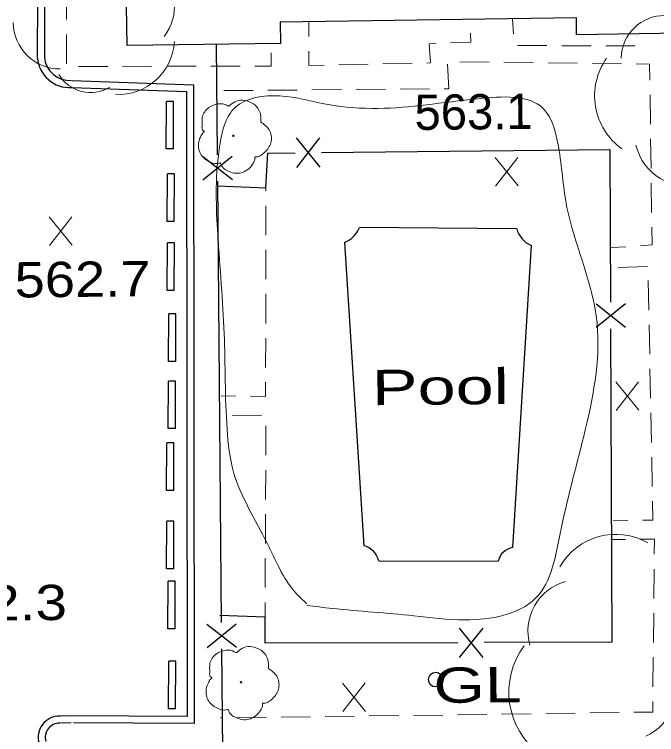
# Model space of a CAD drawing. Extents: x 2361708 to 2370558, y 6977955 to 6991887.
# Drawn here: x 2365980.4 to 2366067.7, y 6986283.8 to 6986381.8 of the extents above; entities that cross this region are included whole.
import ezdxf

# ---------------------------------------------------------------- set-up
doc = ezdxf.new("R2010")
doc.units = 0
doc.header["$LTSCALE"] = 1.9
for name, color, linetype, lineweight in [('11', 7, 'Continuous', 25), ('13', 7, 'Continuous', 13), ('17', 7, 'Continuous', 25), ('2', 7, 'Continuous', 25), ('20', 7, 'Continuous', 25), ('23', 7, 'Continuous', 25), ('29', 7, 'Continuous', 13), ('31', 7, 'Continuous', 13), ('35', 7, 'Continuous', 13)]:
    doc.layers.add(name, color=color, linetype=linetype, lineweight=lineweight)

msp = doc.modelspace()

# ---------------------------------------------------------------- linework, layer by layer
at = {"layer": '11'}
msp.add_lwpolyline([(2366137.4, 6986379.684), (2366107.662, 6986379.311), (2366107.635, 6986381.121), (2366090.917, 6986380.861), (2366090.94, 6986379.542), (2366056.863, 6986378.997), (2366056.831, 6986381.327), (2366016.544, 6986380.754), (2366016.581, 6986377.854), (2365995.733, 6986377.546), (2365995.617, 6986385.604), (2365997.517, 6986385.633), (2365996.969, 6986420.089), (2366039.844, 6986420.767), (2366039.946, 6986414.288), (2366105.78, 6986415.284), (2366105.76, 6986416.304), (2366136.797, 6986416.81)], close=True, dxfattribs=at)
at = {"layer": '13'}
for p, q in [((2365987.512, 6986385.077), (2365987.499, 6986381.077)), ((2366048.162, 6986381.145), (2366048.301, 6986379.146)), ((2366020.444, 6986380.781), (2366020.443, 6986378.781)), ((2365987.489, 6986379.077), (2365987.477, 6986375.077)), ((2366048.836, 6986377.561), (2366052.836, 6986377.549)), ((2366054.837, 6986377.538), (2366058.837, 6986377.526)), ((2366030.519, 6986375.056), (2366034.518, 6986375.144)), ((2366044.977, 6986375.304), (2366040.977, 6986375.346)), ((2366050.978, 6986375.231), (2366046.978, 6986375.283)), ((2366056.979, 6986375.158), (2366052.979, 6986375.21)), ((2366062.98, 6986375.085), (2366058.98, 6986375.137)), ((2365989.12, 6986374.722), (2365993.12, 6986374.73)), ((2365995.12, 6986374.729), (2365999.12, 6986374.738)), ((2366001.12, 6986374.747), (2366005.121, 6986374.755)), ((2366007.121, 6986374.754), (2366011.121, 6986374.762)), ((2366024.52, 6986374.939), (2366028.519, 6986375.017)), ((2366012.872, 6986371.458), (2366008.872, 6986371.43)), ((2366018.872, 6986371.505), (2366014.872, 6986371.477)), ((2366024.872, 6986371.562), (2366020.872, 6986371.524)), ((2366030.872, 6986371.609), (2366026.872, 6986371.581)), ((2366036.872, 6986371.657), (2366032.872, 6986371.628)), ((2366066.899, 6986366.852), (2366066.851, 6986370.852)), ((2366066.986, 6986360.853), (2366066.928, 6986364.852)), ((2366067.073, 6986354.853), (2366067.015, 6986358.853)), ((2366014.602, 6986357.774), (2366014.609, 6986358.184)), ((2366014.6, 6986351.773), (2366014.602, 6986355.774)), ((2366014.587, 6986345.773), (2366014.599, 6986349.773)), ((2366061.558, 6986350.07), (2366063.557, 6986350.199)), ((2366066.503, 6986347.518), (2366062.504, 6986347.369)), ((2366066.689, 6986341.589), (2366066.611, 6986345.588)), ((2366014.584, 6986339.773), (2366014.586, 6986343.773)), ((2366066.806, 6986335.59), (2366066.728, 6986339.589)), ((2366014.581, 6986333.772), (2366014.583, 6986337.773)), ((2366066.923, 6986329.59), (2366066.845, 6986333.59)), ((2366008.528, 6986329.914), (2366010.528, 6986329.884)), ((2366014.023, 6986327.247), (2366010.023, 6986327.269)), ((2366067.04, 6986323.592), (2366066.962, 6986327.591)), ((2366014.595, 6986321.832), (2366014.607, 6986325.832)), ((2366067.157, 6986317.592), (2366067.079, 6986321.592)), ((2366014.572, 6986315.831), (2366014.584, 6986319.832)), ((2366014.539, 6986309.831), (2366014.561, 6986313.831)), ((2366061.822, 6986312.901), (2366063.822, 6986312.95)), ((2366061.536, 6986310.368), (2366063.536, 6986310.397)), ((2366014.516, 6986303.831), (2366014.528, 6986307.831)), ((2366067.414, 6986306.364), (2366067.373, 6986302.364)), ((2366014.494, 6986299.83), (2366014.505, 6986301.831)), ((2366067.352, 6986300.363), (2366067.31, 6986296.363)), ((2366067.289, 6986294.363), (2366067.247, 6986290.362)), ((2366008.675, 6986286.114), (2366008.434, 6986286.111)), ((2366014.674, 6986286.191), (2366010.675, 6986286.143)), ((2366020.674, 6986286.268), (2366016.674, 6986286.22)), ((2366026.673, 6986286.355), (2366022.673, 6986286.297)), ((2366032.673, 6986286.433), (2366028.673, 6986286.384)), ((2366038.672, 6986286.51), (2366034.673, 6986286.461)), ((2366044.672, 6986286.587), (2366040.672, 6986286.539)), ((2366050.671, 6986286.674), (2366046.672, 6986286.616)), ((2366056.671, 6986286.761), (2366052.671, 6986286.703)), ((2366062.67, 6986286.848), (2366058.671, 6986286.79))]:
    msp.add_line(p, q, dxfattribs=at)
for points in [[(2366039.733, 6986377.904), (2366042.482, 6986378), (2366042.44, 6986379.25)], [(2366036.518, 6986375.183), (2366037.008, 6986375.198), (2366036.833, 6986377.806), (2366037.733, 6986377.835)], [(2366060.837, 6986377.525), (2366064.767, 6986377.512), (2366064.777, 6986377.583)], [(2366013.121, 6986374.771), (2366015.321, 6986374.772), (2366015.314, 6986376.572)], [(2366020.442, 6986376.781), (2366020.441, 6986374.861), (2366022.52, 6986374.9)], [(2366039.329, 6986375.04), (2366039.511, 6986371.682), (2366038.872, 6986371.676)], [(2366066.821, 6986372.851), (2366066.791, 6986375.042), (2366064.981, 6986375.064)], [(2366065.556, 6986350.328), (2366067.135, 6986350.433), (2366067.102, 6986352.854)], [(2366012.528, 6986329.853), (2366014.579, 6986329.822), (2366014.58, 6986331.773)], [(2366065.821, 6986312.989), (2366067.251, 6986313.023), (2366067.196, 6986315.592)], [(2366065.536, 6986310.426), (2366067.456, 6986310.445), (2366067.435, 6986308.364)], [(2366067.236, 6986288.362), (2366067.22, 6986286.911), (2366064.67, 6986286.877)]]:
    msp.add_lwpolyline(points, dxfattribs=at)
at = {"layer": '17'}
for p, q in [((2366007.863, 6986377.701), (2366007.995, 6986362.701)), ((2366022.002, 6986361.014), (2366018.754, 6986364.984)), ((2366018.803, 6986360.984), (2366021.954, 6986365.014)), ((2366006.028, 6986362.483), (2366010.058, 6986359.321)), ((2366006.058, 6986359.283), (2366010.027, 6986362.521)), ((2366008.03, 6986359.101), (2366008.551, 6986299.103)), ((2366059.511, 6986342.441), (2366063.521, 6986339.259)), ((2366059.521, 6986339.241), (2366063.511, 6986342.459)), ((2366006.583, 6986298.885), (2366010.613, 6986295.723)), ((2366006.614, 6986295.685), (2366010.583, 6986298.923)), ((2366040.91, 6986298.321), (2366044.118, 6986294.332)), ((2366044.11, 6986298.332), (2366040.918, 6986294.322)), ((2366008.585, 6986295.504), (2366008.707, 6986281.614))]:
    msp.add_line(p, q, dxfattribs=at)
for points in [[(2366022.183, 6986362.996), (2366061.391, 6986363.439), (2366061.479, 6986342.649)], [(2366008.035, 6986358.492), (2366014.609, 6986358.184), (2366014.894, 6986362.907), (2366018.584, 6986362.952)], [(2366061.493, 6986339.05), (2366061.669, 6986296.409), (2366044.309, 6986296.364)], [(2366040.709, 6986296.35), (2366014.508, 6986296.28), (2366014.494, 6986299.83), (2366008.342, 6986300.032)]]:
    msp.add_lwpolyline(points, dxfattribs=at)
at = {"layer": '2'}
for p, q in [((2365983.72, 6986446.114), (2365983.528, 6986375.929)), ((2365984.681, 6986446.113), (2365984.489, 6986375.928)), ((2366001.068, 6986363.495), (2366001.096, 6986369.966)), ((2366002.056, 6986369.965), (2366001.096, 6986369.966)), ((2366002.028, 6986363.494), (2366002.056, 6986369.965)), ((2366002.028, 6986363.494), (2366001.068, 6986363.495)), ((2366001.191, 6986353.646), (2366001.22, 6986360.117)), ((2366002.18, 6986360.116), (2366001.22, 6986360.117)), ((2366002.151, 6986353.645), (2366002.18, 6986360.116)), ((2366002.151, 6986353.645), (2366001.191, 6986353.646)), ((2366001.181, 6986344.255), (2366001.209, 6986350.726)), ((2366002.169, 6986350.725), (2366001.209, 6986350.726)), ((2366002.141, 6986344.255), (2366002.169, 6986350.725)), ((2366002.141, 6986344.255), (2366001.181, 6986344.255)), ((2366001.383, 6986334.607), (2366001.411, 6986341.077)), ((2366002.371, 6986341.077), (2366001.411, 6986341.077)), ((2366002.343, 6986334.606), (2366002.371, 6986341.077)), ((2366002.343, 6986334.606), (2366001.383, 6986334.607)), ((2366001.34, 6986325.456), (2366001.368, 6986331.927)), ((2366002.328, 6986331.926), (2366001.368, 6986331.927)), ((2366002.3, 6986325.455), (2366002.328, 6986331.926)), ((2366002.3, 6986325.455), (2366001.34, 6986325.456)), ((2366001.11, 6986317.044), (2366001.138, 6986323.514)), ((2366002.098, 6986323.514), (2366001.138, 6986323.514)), ((2366002.07, 6986317.043), (2366002.098, 6986323.514)), ((2366002.07, 6986317.043), (2366001.11, 6986317.044)), ((2366001.111, 6986306.393), (2366001.14, 6986312.864)), ((2366002.099, 6986312.863), (2366001.14, 6986312.864)), ((2366002.071, 6986306.392), (2366002.099, 6986312.863)), ((2366002.071, 6986306.392), (2366001.111, 6986306.393)), ((2366001.299, 6986298.244), (2366001.327, 6986304.715)), ((2366002.287, 6986304.714), (2366001.327, 6986304.715)), ((2366002.259, 6986298.244), (2366002.287, 6986304.714)), ((2366002.259, 6986298.244), (2366001.299, 6986298.244)), ((2366001.372, 6986287.355), (2366001.401, 6986293.825)), ((2366002.361, 6986293.824), (2366001.401, 6986293.825)), ((2366002.332, 6986287.354), (2366002.361, 6986293.824)), ((2366002.332, 6986287.354), (2366001.372, 6986287.355)), ((2365988.101, 6986286.398), (2365986.621, 6986286.344)), ((2365988.14, 6986285.438), (2365986.661, 6986285.384))]:
    msp.add_line(p, q, dxfattribs=at)
for points in [[(2365988.268, 6986372.814), (2366004.775, 6986372.221), (2366004.872, 6986285.358), (2365988.43, 6986285.431)], [(2365988.237, 6986371.853), (2366003.814, 6986371.292), (2366003.912, 6986286.318), (2365988.101, 6986286.398)]]:
    msp.add_lwpolyline(points, dxfattribs=at)
for centre, radius, start, end in [((2365987.93, 6986376.256), 4.414, 184.24794, 273.99548), ((2365987.93, 6986376.256), 3.454, 184.24794, 273.99548), ((2365986.503, 6986283.487), 2.86, 87.62847, 197.50948), ((2365986.503, 6986283.487), 1.9, 87.62847, 197.50948)]:
    msp.add_arc(centre, radius, start, end, dxfattribs=at)
at = {"layer": '20'}
msp.add_circle((2366037.716, 6986291.321), 1, dxfattribs=at)
at = {"layer": '23'}
for p, q in [((2366048.723, 6986352.638), (2366027.331, 6986352.795)), ((2366025.31, 6986350.775), (2366027.943, 6986309.539)), ((2366048.186, 6986309.291), (2366050.715, 6986350.347)), ((2366029.962, 6986307.488), (2366046.213, 6986307.442))]:
    msp.add_line(p, q, dxfattribs=at)
for centre, radius, start, end in [((2366023.941, 6986354.166), 3.657, 291.98338, 337.97284), ((2366052.046, 6986353.514), 3.434, 194.75687, 247.20653), ((2366027.168, 6986306.757), 2.887, 14.65909, 74.44606), ((2366048.549, 6986306.926), 2.392, 98.73214, 167.53693)]:
    msp.add_arc(centre, radius, start, end, dxfattribs=at)
at = {"layer": '29'}
for centre in [(2366010.191, 6986365.282), (2366011.228, 6986290.969)]:
    msp.add_circle(centre, 0.1, dxfattribs=at)
for centre, radius, start, end in [((2365995.831, 6986382.768), 6.34, 321.26488, 51.26488), ((2366068.808, 6986375.761), 5.875, 89.11329, 179.11329), ((2365986.605, 6986380.715), 6.34, 180.31255, 270.31255), ((2365994.572, 6986378.516), 7.604, 266.76394, 356.76394), ((2366068.136, 6986370.712), 8.818, 144.59869, 234.59869), ((2365990.785, 6986376.244), 5.067, 211.06469, 301.06469), ((2366072.055, 6986365.786), 7.352, 193.80787, 283.80787), ((2366062.193, 6986302.312), 8.768, 60.13986, 150.13986), ((2366057.252, 6986297.927), 7.007, 105.74577, 195.74577), ((2366058.174, 6986289.628), 10.517, 143.17482, 233.17482), ((2366063.417, 6986290.031), 7.007, 294.05872, 24.05872)]:
    msp.add_arc(centre, radius, start, end, dxfattribs=at)
for points in [[(2366006.225, 6986365.854), (2366006.245, 6986365.865), (2366006.165, 6986365.934), (2366005.929, 6986366.562), (2366005.967, 6986367.842), (2366006.854, 6986369.141), (2366008.16, 6986369.623), (2366009.281, 6986369.434), (2366009.513, 6986369.306), (2366009.582, 6986369.307), (2366009.632, 6986369.347), (2366009.979, 6986369.641), (2366010.846, 6986370.089), (2366012.056, 6986370.02), (2366013.172, 6986369.431), (2366013.905, 6986368.008), (2366013.913, 6986367.148)], [(2366013.903, 6986367.168), (2366015.043, 6986366.108), (2366015.328, 6986364.521), (2366014.621, 6986363.195), (2366013.966, 6986362.648), (2366013.298, 6986362.432), (2366013.148, 6986362.42), (2366013.13, 6986362.31), (2366012.808, 6986361.407), (2366011.269, 6986360.242), (2366009.376, 6986360.524), (2366008.477, 6986361.466), (2366008.406, 6986361.595), (2366008.286, 6986361.574), (2366007.075, 6986361.692), (2366005.806, 6986362.691), (2366005.46, 6986364.327), (2366005.83, 6986365.351), (2366006.156, 6986365.794), (2366006.225, 6986365.845)], [(2366007.263, 6986291.541), (2366007.283, 6986291.551), (2366007.202, 6986291.62), (2366006.966, 6986292.248), (2366007.004, 6986293.528), (2366007.891, 6986294.827), (2366009.197, 6986295.31), (2366010.319, 6986295.12), (2366010.55, 6986294.993), (2366010.62, 6986294.993), (2366010.67, 6986295.034), (2366011.017, 6986295.327), (2366011.883, 6986295.775), (2366013.094, 6986295.707), (2366014.209, 6986295.117), (2366014.943, 6986293.694), (2366014.951, 6986292.834)], [(2366014.941, 6986292.854), (2366016.081, 6986291.795), (2366016.366, 6986290.208), (2366015.659, 6986288.881), (2366015.004, 6986288.334), (2366014.336, 6986288.118), (2366014.186, 6986288.107), (2366014.167, 6986287.997), (2366013.846, 6986287.094), (2366012.306, 6986285.929), (2366010.414, 6986286.21), (2366009.515, 6986287.152), (2366009.443, 6986287.282), (2366009.324, 6986287.26), (2366008.113, 6986287.379), (2366006.843, 6986288.377), (2366006.497, 6986290.014), (2366006.868, 6986291.037), (2366007.193, 6986291.48), (2366007.263, 6986291.531)]]:
    msp.add_spline(points, degree=3, dxfattribs=at)
at = {"layer": '31'}
for p, q in [((2366048.908, 6986358.461), (2366045.791, 6986362.311)), ((2366045.828, 6986358.431), (2366048.871, 6986362.34)), ((2365988.271, 6986350.393), (2365985.155, 6986354.243)), ((2365985.192, 6986350.364), (2365988.234, 6986354.273)), ((2366065.309, 6986327.965), (2366062.192, 6986331.816)), ((2366062.229, 6986327.936), (2366065.272, 6986331.845)), ((2366028.137, 6986287), (2366025.02, 6986290.85)), ((2366025.057, 6986286.97), (2366028.1, 6986290.879))]:
    msp.add_line(p, q, dxfattribs=at)
at = {"layer": '35'}
msp.add_spline([(2366020.159, 6986301.415), (2366023.634, 6986301.007), (2366034.714, 6986300.002), (2366041.699, 6986299.439), (2366051.282, 6986302.381), (2366054.772, 6986311.834), (2366058.044, 6986325.276), (2366059.537, 6986340.781), (2366055.556, 6986355.554), (2366054.493, 6986363.264), (2366052.328, 6986369.004), (2366043.434, 6986370.329), (2366029.846, 6986369.01), (2366023.071, 6986369.535), (2366016.47, 6986370.712), (2366010.504, 6986369.206), (2366008.249, 6986363.394), (2366008.069, 6986351.781), (2366008.937, 6986338.369), (2366009.33, 6986325.412), (2366010.216, 6986319.55), (2366014.788, 6986309.884), (2366018.582, 6986303.209), (2366020.167, 6986301.654)], degree=3, dxfattribs=at)

# ---------------------------------------------------------------- texts
at = {"layer": '20', "width": 1.4}
msp.add_text('  GL', height=4.8, rotation=0.545, dxfattribs=at).set_placement((2366032.427, 6986288.101))
at = {"layer": '23', "width": 1.45}
msp.add_text('Pool', height=4.8, rotation=0.545, dxfattribs=at).set_placement((2366029.051, 6986328.64))
at = {"layer": '31'}
msp.add_text('563.1', height=4.8, rotation=0.545, dxfattribs=at).set_placement((2366034.845, 6986366.067))
for s, width, p in [('562.7', 1.15, (2365980.459, 6986343.288)), ('562.3', 1.2, (2365968.308, 6986299.26))]:
    msp.add_text(s, height=4.8, rotation=0.545, dxfattribs=dict(at, width=width)).set_placement(p)

doc.saveas('drawing.dxf')
